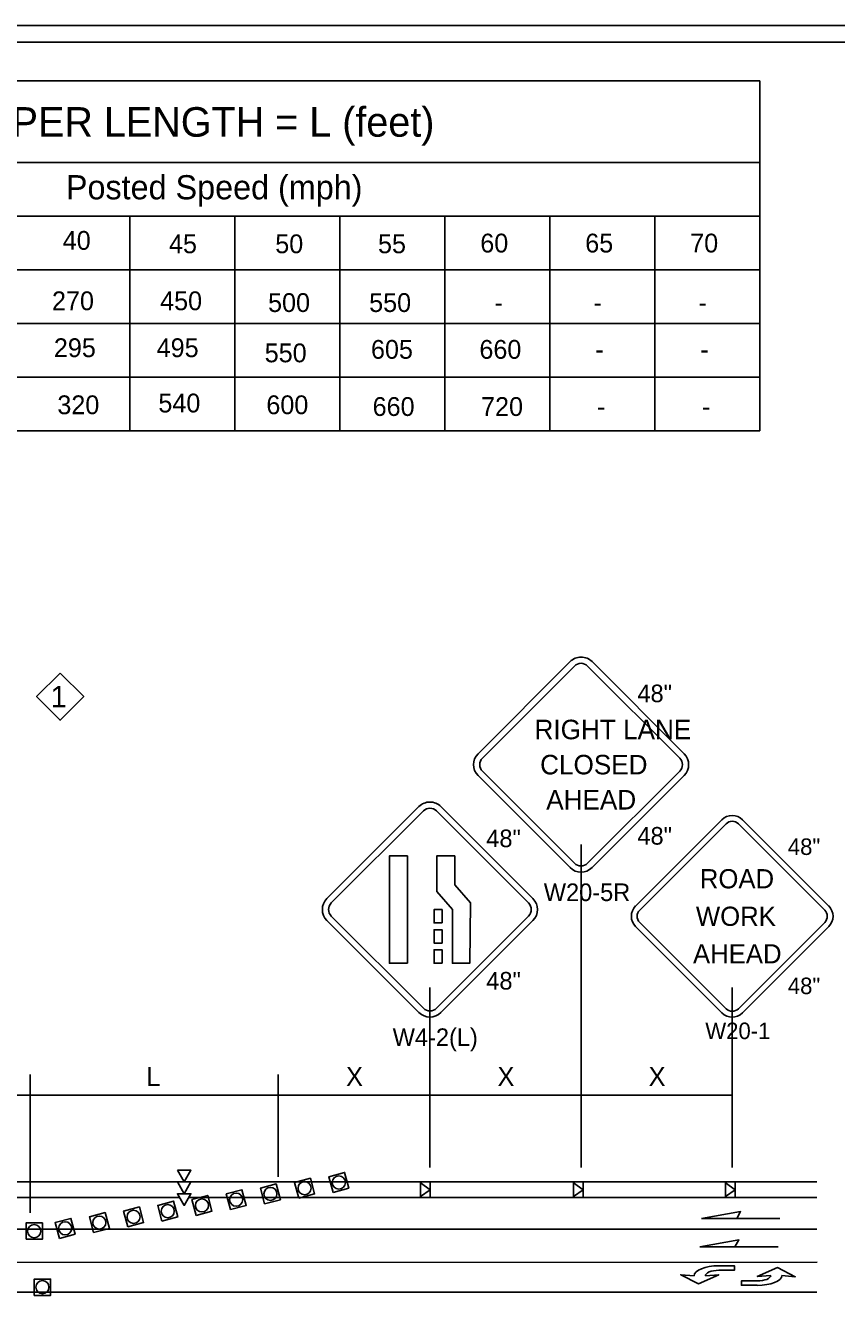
# Model space of a CAD drawing. Extents: x 99988 to 100172, y 99995 to 100047.
# Drawn here: x 100007.533 to 100010.552, y 100005.686 to 100010.437 of the extents above; entities that cross this region are included whole.
import ezdxf

# ---------------------------------------------------------------- set-up
doc = ezdxf.new("R2010")
doc.units = 0
for name, color, linetype in [('Default', 7, 'Continuous'), ('Level 15', 7, 'Continuous'), ('Level 20', 7, 'Continuous'), ('RD_MK_TrafficArrowType2LNew', 7, 'Continuous'), ('SH_DE_DetailBody1Text', 7, 'Continuous'), ('SH_GI_PlotLimits', 7, 'Continuous'), ('SH_GI_SheetBorder', 7, 'Continuous'), ('SH_GI_TrafficMvmntArrowRt1Lane', 7, 'Continuous'), ('SH_TI_MinTaperLength25to70Note', 7, 'Continuous'), ('SH_TI_SignSpacing35to70Note', 7, 'Continuous'), ('TR_SN_WarningSigns', 7, 'Continuous'), ('TR_WZ_TrafficSafetyCone', 7, 'Continuous'), ('TR_WZ_WorkZoneDetails', 7, 'Continuous')]:
    doc.layers.add(name, color=color, linetype=linetype)

msp = doc.modelspace()

# ---------------------------------------------------------------- linework, layer by layer
at = {"layer": 'Default'}
for p, q in [((100009.0033, 100006.1278), (100009.0399, 100006.1024)), ((100009.0033, 100006.1278), (100009.0033, 100006.0769)), ((100009.0033, 100006.0769), (100009.0399, 100006.1024)), ((100009.0399, 100006.1278), (100009.0399, 100006.0769)), ((100009.5722, 100006.1278), (100009.6088, 100006.1024)), ((100009.5722, 100006.1278), (100009.5722, 100006.0769)), ((100009.5722, 100006.0769), (100009.6088, 100006.1024)), ((100009.6088, 100006.1278), (100009.6088, 100006.0769)), ((100010.1382, 100006.1278), (100010.1748, 100006.1024)), ((100010.1382, 100006.1278), (100010.1382, 100006.0769)), ((100010.1382, 100006.0769), (100010.1748, 100006.1024)), ((100010.1748, 100006.1278), (100010.1748, 100006.0769)), ((100010.4792, 100005.833), (100006.3963, 100005.8313))]:
    msp.add_line(p, q, dxfattribs=at)
at = {"layer": 'Level 15'}
for p, q in [((100007.5506, 100006.4539), (100006.8541, 100006.4539)), ((100007.5506, 100006.4539), (100008.0122, 100006.4539)), ((100008.4737, 100006.4539), (100008.0122, 100006.4539)), ((100008.4737, 100006.4539), (100008.7561, 100006.4539)), ((100009.0385, 100006.4539), (100008.7561, 100006.4539)), ((100009.0385, 100006.4539), (100009.3198, 100006.4539)), ((100009.601, 100006.4539), (100009.3198, 100006.4539)), ((100009.601, 100006.4539), (100009.8823, 100006.4539)), ((100010.1635, 100006.4539), (100009.8823, 100006.4539))]:
    msp.add_line(p, q, dxfattribs=at)
at = {"layer": 'RD_MK_TrafficArrowType2LNew'}
for p, q in [((100010.1136, 100005.8192), (100010.1136, 100005.8192)), ((100010.1136, 100005.8192), (100010.1136, 100005.8192)), ((100010.0219, 100005.7817), (100010.0219, 100005.7817)), ((100010.0636, 100005.7817), (100010.0636, 100005.7817)), ((100010.1136, 100005.8025), (100010.1136, 100005.8025)), ((100010.2566, 100005.763), (100010.2566, 100005.763)), ((100010.3068, 100005.7833), (100010.3068, 100005.7833)), ((100010.3485, 100005.7829), (100010.3485, 100005.7829)), ((100010.2565, 100005.7464), (100010.2565, 100005.7464)), ((100010.2565, 100005.7464), (100010.2565, 100005.7464))]:
    msp.add_line(p, q, dxfattribs=at)
for points in [[(100010.1136, 100005.8192), (100010.1719, 100005.8192), (100010.1719, 100005.8025), (100010.1136, 100005.8025)], [(100010.3068, 100005.7833), (100010.2568, 100005.7797), (100010.3321, 100005.8123), (100010.3985, 100005.7783), (100010.3485, 100005.7829)], [(100010.0636, 100005.7817), (100010.1136, 100005.7858), (100010.0386, 100005.7525), (100009.9719, 100005.7858), (100010.0219, 100005.7817)], [(100010.2565, 100005.7464), (100010.1981, 100005.7469), (100010.1983, 100005.7636), (100010.2566, 100005.763)]]:
    msp.add_lwpolyline(points, dxfattribs=at)
for centre, major_axis, ratio, start_param in [((100010.1136, 100005.7817), (-0.0917, 0), 0.40879, 4.712524), ((100010.1136, 100005.7817), (-0.05, 0), 0.41611, 4.712518), ((100010.2568, 100005.7838), (0.0917, -0.0009), 0.40879, 4.712524), ((100010.2568, 100005.7838), (0.05, -0.0005), 0.41611, 4.712518)]:
    msp.add_ellipse(centre, major_axis=major_axis, ratio=ratio, start_param=start_param, end_param=6.283185, dxfattribs=at)
at = {"layer": 'SH_DE_DetailBody1Text'}
msp.add_lwpolyline([(100007.6621, 100008.0263), (100007.7499, 100007.9385), (100007.6621, 100007.8507), (100007.5744, 100007.9385)], close=True, dxfattribs=at)
at = {"layer": 'SH_GI_PlotLimits'}
msp.add_lwpolyline([(99999.3125, 99999.9375), (100015.8125, 99999.9375), (100015.8125, 100010.4375), (99999.3125, 100010.4375)], close=True, dxfattribs=at)
at = {"layer": 'SH_GI_SheetBorder'}
msp.add_line((100000, 100010.375), (100015.75, 100010.375), dxfattribs=at)
at = {"layer": 'SH_GI_TrafficMvmntArrowRt1Lane'}
for p, q in [((100010.1802, 100005.9956), (100010.3409, 100005.9956)), ((100010.1735, 100005.8898), (100010.3343, 100005.8898))]:
    msp.add_line(p, q, dxfattribs=at)
for points in [[(100010.0491, 100005.9956), (100010.195, 100006.0213), (100010.1802, 100005.9956)], [(100010.0425, 100005.8898), (100010.1884, 100005.9155), (100010.1735, 100005.8898)]]:
    msp.add_lwpolyline(points, close=True, dxfattribs=at)
at = {"layer": 'SH_TI_MinTaperLength25to70Note'}
for p, q in [((100005.766, 100009.9279), (100010.2661, 100009.9279)), ((100006.3592, 100009.7279), (100010.2661, 100009.7279)), ((100007.9219, 100009.7279), (100007.9219, 100008.9279)), ((100008.3126, 100009.7279), (100008.3126, 100008.9279)), ((100008.7033, 100009.7279), (100008.7033, 100008.9279)), ((100009.094, 100009.7279), (100009.094, 100008.9279)), ((100009.4846, 100009.7279), (100009.4846, 100008.9279)), ((100009.8752, 100009.7279), (100009.8752, 100008.9279)), ((100005.766, 100009.5279), (100010.2661, 100009.5279)), ((100005.766, 100009.3279), (100010.2661, 100009.3279)), ((100005.766, 100009.1279), (100010.2661, 100009.1279))]:
    msp.add_line(p, q, dxfattribs=at)
at = {"layer": 'SH_TI_SignSpacing35to70Note'}
for p, q in [((100005.766, 100010.2311), (100010.2661, 100010.2311)), ((100010.2661, 100010.2311), (100010.2661, 100008.9279)), ((100005.766, 100008.9279), (100010.2661, 100008.9279))]:
    msp.add_line(p, q, dxfattribs=at)
at = {"layer": 'TR_SN_WarningSigns'}
for p, q in [((100009.2175, 100007.7261), (100009.5602, 100008.0688)), ((100009.2339, 100007.7098), (100009.5766, 100008.0525)), ((100009.6255, 100008.0525), (100009.9682, 100007.7098)), ((100009.6418, 100008.0688), (100009.9845, 100007.7261)), ((100009.5766, 100007.3182), (100009.2339, 100007.6609)), ((100009.9682, 100007.6609), (100009.6255, 100007.3182)), ((100009.5602, 100007.3019), (100009.2175, 100007.6445)), ((100009.9845, 100007.6445), (100009.6418, 100007.3019)), ((100008.655, 100007.1865), (100008.9977, 100007.5291)), ((100009.0793, 100007.5291), (100009.422, 100007.1865)), ((100008.6714, 100007.1701), (100009.0141, 100007.5128)), ((100009.063, 100007.5128), (100009.4057, 100007.1701)), ((100009.804, 100007.1589), (100010.1253, 100007.4802)), ((100010.2018, 100007.4802), (100010.523, 100007.1589)), ((100009.8193, 100007.1436), (100010.1406, 100007.4649)), ((100010.1865, 100007.4649), (100010.5077, 100007.1436)), ((100008.9977, 100006.7622), (100008.655, 100007.1049)), ((100009.0141, 100006.7785), (100008.6714, 100007.1212)), ((100009.4057, 100007.1212), (100009.063, 100006.7785)), ((100009.422, 100007.1049), (100009.0793, 100006.7622)), ((100010.1406, 100006.7764), (100009.8193, 100007.0977)), ((100010.5077, 100007.0977), (100010.1865, 100006.7764)), ((100010.1253, 100006.7611), (100009.804, 100007.0824)), ((100010.523, 100007.0824), (100010.2018, 100006.7611))]:
    msp.add_line(p, q, dxfattribs=at)
for points in [[(100008.9549, 100006.9457), (100008.8877, 100006.9457), (100008.8877, 100007.3457), (100008.9549, 100007.3457)], [(100009.1309, 100007.3457), (100009.1309, 100007.2378), (100009.1893, 100007.1709), (100009.1864, 100006.9457), (100009.1221, 100006.9457), (100009.1221, 100007.1457), (100009.0637, 100007.2126), (100009.0637, 100007.3457)], [(100009.0838, 100007.0957), (100009.0541, 100007.0957), (100009.0541, 100007.1457), (100009.0838, 100007.1457)], [(100009.0838, 100007.0207), (100009.0541, 100007.0207), (100009.0541, 100007.0707), (100009.0838, 100007.0707)], [(100009.0838, 100006.9457), (100009.0541, 100006.9457), (100009.0541, 100006.9957), (100009.0838, 100006.9957)]]:
    msp.add_lwpolyline(points, close=True, dxfattribs=at)
for centre, radius, start, end in [((100009.601, 100008.028), 0.0577, 44.9963, 134.9997), ((100009.601, 100008.028), 0.0346, 44.9963, 134.9997), ((100009.2584, 100007.6853), 0.0577, 134.9966, 224.9936), ((100009.2584, 100007.6853), 0.0346, 134.9966, 224.9936), ((100009.9437, 100007.6853), 0.0346, 314.9994, 44.9948), ((100009.9437, 100007.6853), 0.0577, 314.9994, 44.9948), ((100009.0385, 100007.4884), 0.0577, 44.9963, 134.9997), ((100009.0385, 100007.4884), 0.0346, 44.9963, 134.9997), ((100010.1635, 100007.4419), 0.0541, 44.9963, 134.9997), ((100010.1635, 100007.4419), 0.0325, 44.9963, 134.9997), ((100009.601, 100007.3427), 0.0577, 225, 314.9996), ((100009.601, 100007.3427), 0.0346, 225, 314.9996), ((100008.6958, 100007.1457), 0.0577, 134.9966, 224.9936), ((100009.3812, 100007.1457), 0.0577, 314.9994, 44.9948), ((100008.6958, 100007.1457), 0.0346, 134.9966, 224.9936), ((100009.3812, 100007.1457), 0.0346, 314.9994, 44.9948), ((100009.8423, 100007.1207), 0.0541, 134.9966, 224.9936), ((100009.8423, 100007.1207), 0.0325, 134.9966, 224.9936), ((100010.4848, 100007.1207), 0.0325, 314.9994, 44.9948), ((100010.4848, 100007.1207), 0.0541, 314.9994, 44.9948), ((100009.0385, 100006.803), 0.0577, 225, 314.9996), ((100009.0385, 100006.803), 0.0346, 225, 314.9996), ((100010.1635, 100006.7994), 0.0541, 225, 314.9996), ((100010.1635, 100006.7994), 0.0325, 225, 314.9996)]:
    msp.add_arc(centre, radius, start, end, dxfattribs=at)
at = {"layer": 'TR_WZ_TrafficSafetyCone'}
for points in [[(100008.5504, 100006.0709), (100008.6091, 100006.0867), (100008.5934, 100006.1453), (100008.5347, 100006.1296)], [(100008.6778, 100006.0923), (100008.7364, 100006.108), (100008.7207, 100006.1667), (100008.662, 100006.151)], [(100008.2958, 100006.0282), (100008.3545, 100006.0439), (100008.3387, 100006.1026), (100008.2801, 100006.0869)], [(100008.4231, 100006.0496), (100008.4818, 100006.0653), (100008.4661, 100006.124), (100008.4074, 100006.1082)], [(100008.0411, 100005.9855), (100008.0998, 100006.0012), (100008.0841, 100006.0599), (100008.0254, 100006.0441)], [(100008.1685, 100006.0068), (100008.2271, 100006.0226), (100008.2114, 100006.0812), (100008.1527, 100006.0655)], [(100007.7865, 100005.9427), (100007.8452, 100005.9585), (100007.8294, 100006.0171), (100007.7708, 100006.0014)], [(100007.9138, 100005.9641), (100007.9725, 100005.9798), (100007.9568, 100006.0385), (100007.8981, 100006.0228)], [(100007.5352, 100005.9178), (100007.5959, 100005.9178), (100007.5959, 100005.9786), (100007.5352, 100005.9786)], [(100007.6592, 100005.9214), (100007.7178, 100005.9371), (100007.7021, 100005.9958), (100007.6435, 100005.98)], [(100007.5657, 100005.709), (100007.6264, 100005.709), (100007.6264, 100005.7698), (100007.5657, 100005.7698)]]:
    msp.add_lwpolyline(points, close=True, dxfattribs=at)
for centre in [(100008.6992, 100006.1295), (100008.4446, 100006.0868), (100008.5719, 100006.1081), (100008.0626, 100006.0227), (100008.1899, 100006.044), (100008.3173, 100006.0654), (100007.808, 100005.9799), (100007.9353, 100006.0013), (100007.5655, 100005.9482), (100007.6807, 100005.9586), (100007.5961, 100005.7394)]:
    msp.add_circle(centre, 0.0244, dxfattribs=at)
at = {"layer": 'TR_WZ_WorkZoneDetails'}
for p, q in [((100009.601, 100006.1854), (100009.601, 100007.3881)), ((100009.0385, 100006.1854), (100009.0385, 100006.8556)), ((100010.1635, 100006.1854), (100010.1635, 100006.8556)), ((100007.5506, 100006.5317), (100007.5506, 100006.0167)), ((100008.4737, 100006.5317), (100008.4737, 100006.1509)), ((100007.2729, 100006.1318), (100008.0987, 100006.1318)), ((100008.149, 100006.1318), (100010.4791, 100006.1318)), ((100007.2729, 100006.0731), (100008.1042, 100006.0731)), ((100008.1422, 100006.0731), (100010.4791, 100006.0731)), ((100005.5914, 100005.9557), (100010.4791, 100005.9557)), ((100005.5945, 100005.7212), (100010.4791, 100005.7212))]:
    msp.add_line(p, q, dxfattribs=at)
msp.add_lwpolyline([(100008.0985, 100006.1749), (100008.149, 100006.1749), (100008.1238, 100006.1313), (100008.149, 100006.1313), (100008.1238, 100006.0877), (100008.149, 100006.0877), (100008.1238, 100006.0441), (100008.0985, 100006.0877), (100008.1238, 100006.0877), (100008.0985, 100006.1313), (100008.1238, 100006.1313)], close=True, dxfattribs=at)

# ---------------------------------------------------------------- texts
at = {"layer": 'Level 20'}
for s, p in [('L', (100007.9831, 100006.4889)), ('X', (100008.7264, 100006.4889)), ('X', (100009.2901, 100006.4889)), ('X', (100009.8526, 100006.4889))]:
    msp.add_text(s, height=0.07, rotation=360, dxfattribs=at).set_placement(p)
at = {"layer": 'SH_DE_DetailBody1Text'}
msp.add_text('1', height=0.08, dxfattribs=at).set_placement((100007.627, 100007.8985))
at = {"layer": 'SH_TI_MinTaperLength25to70Note'}
for s, height, p in [('MINIMUM TAPER LENGTH = L (feet)', 0.11, (100006.591, 100010.0235)), ('Posted Speed (mph)', 0.09, (100007.6835, 100009.7903)), ('40', 0.07, (100007.6717, 100009.6024)), ('45', 0.07, (100008.0671, 100009.5896)), ('50', 0.07, (100008.4627, 100009.5896)), ('55', 0.07, (100008.8451, 100009.5896)), ('60', 0.07, (100009.2259, 100009.5924)), ('65', 0.07, (100009.6165, 100009.5924)), ('70', 0.07, (100010.0072, 100009.5924)), ('270', 0.07, (100007.6317, 100009.3774)), ('450', 0.07, (100008.0342, 100009.3774)), ('500', 0.07, (100008.436, 100009.3708)), ('550', 0.07, (100008.8122, 100009.3708)), ('-', 0.07, (100009.2786, 100009.3708)), ('-', 0.07, (100009.6473, 100009.3708)), ('-', 0.07, (100010.0383, 100009.3708)), ('295', 0.07, (100007.6387, 100009.2027)), ('495', 0.07, (100008.0213, 100009.2027)), ('550', 0.07, (100008.4234, 100009.1835)), ('605', 0.07, (100008.8189, 100009.1966)), ('660', 0.07, (100009.2225, 100009.1966)), ('-', 0.07, (100009.654, 100009.1966)), ('-', 0.07, (100010.045, 100009.1966)), ('320', 0.07, (100007.6517, 100008.9902)), ('540', 0.07, (100008.0277, 100008.9968)), ('600', 0.07, (100008.4296, 100008.9902)), ('660', 0.07, (100008.8251, 100008.9837)), ('720', 0.07, (100009.2288, 100008.9837)), ('-', 0.07, (100009.6603, 100008.9837)), ('-', 0.07, (100010.0512, 100008.9837))]:
    msp.add_text(s, height=height, dxfattribs=at).set_placement(p)
at = {"layer": 'TR_SN_WarningSigns'}
for s, height, p in [('48"', 0.06563, (100009.8107, 100007.9177)), ('RIGHT LANE', 0.07268, (100009.4279, 100007.7798)), ('CLOSED', 0.07268, (100009.4486, 100007.649)), ('AHEAD', 0.07268, (100009.4713, 100007.5182)), ('48"', 0.06563, (100009.2482, 100007.378)), ('48"', 0.06563, (100009.8107, 100007.3874)), ('48"', 0.06152, (100010.3706, 100007.349)), ('ROAD', 0.07155, (100010.0431, 100007.2246)), ('W20-5R', 0.06563, (100009.4622, 100007.1772)), ('WORK', 0.07155, (100010.0284, 100007.0849)), ('AHEAD', 0.07155, (100010.0176, 100006.9452)), ('48"', 0.06563, (100009.2482, 100006.8477)), ('48"', 0.06152, (100010.3706, 100006.8308)), ('W20-1', 0.06152, (100010.0634, 100006.6632)), ('W4-2(L)', 0.06563, (100008.8998, 100006.6375))]:
    msp.add_text(s, height=height, dxfattribs=at).set_placement(p)

doc.saveas('drawing.dxf')
